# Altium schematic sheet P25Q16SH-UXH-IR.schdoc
size 127 x 101 mm
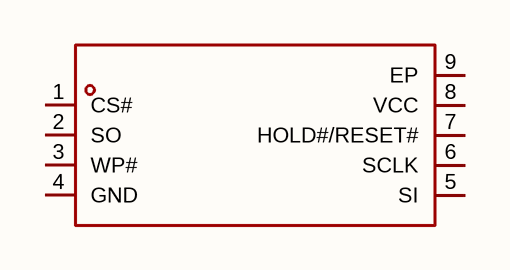
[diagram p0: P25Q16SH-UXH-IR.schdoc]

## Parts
U?  p25q16sh-uxh-ir  [USON8_L3.0-W2.0-P0.50-BL-EP]  (value not drawn)

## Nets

Not connected (* = marked no-connect by the designer): U? 1(CS#) 2(SO) 3(WP#) 4(GND) 5(SI) 6(SCLK) 7(HOLD#/RESET#) 8(VCC) 9(EP)

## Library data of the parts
U? = p25q16sh-uxh-ir: 接口类型:SPI;存储容量:16Mbit;时钟频率(fc):133MHz;; Manufacturer: PUYA(普冉); AddInBom: yes; ModelId: 12a239e5c7384371915ecb51201bf581; ModelName: USON-8_L3.0-W2.0-H0.6-P0.50; ModelTransform: 118.8974,78.74,0,90,0,0,0,0,0; Interface: SPI; Memory Size: 16Mbit; Clock Frequency: 133MHz; Voltage - Supply: 2.3V~3.6V; Standby Supply Current: 10uA; Program / Erase Cycles: 100000次; Write Cycle Time (tWC): 8ms; Page Programming Time (Tpp): 1.5ms; Block Erase Time(tBE): 16ms; Data Retention - TDR (Year): 20年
